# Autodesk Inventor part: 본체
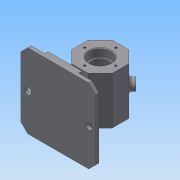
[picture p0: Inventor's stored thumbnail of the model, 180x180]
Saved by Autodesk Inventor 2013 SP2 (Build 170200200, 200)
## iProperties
Created: 2018-06
Part Number: 본체
Material: 일반
Document SubType Name: Modeling
Designer: Administrator
Density: 1 g/cm^3
Author: Administrator
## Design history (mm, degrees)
sketch "스케치1"
  geometry: L1 (-55, -57)-(55, -57); L2 (55, -57)-(55, -62); L3 (55, -62)-(-55, -62); L4 (-55, -62)-(-55, -57); L5 (12.426, 30)-(30, 12.426); L6 (30, 12.426)-(30, -12.426); L7 (30, -12.426)-(12.426, -30); L8 (12.426, -30)-(-12.426, -30); L9 (-12.426, -30)-(-30, -12.426); L10 (-30, -12.426)-(-30, 12.426); L11 (-30, 12.426)-(-12.426, 30); L12 (-12.426, 30)-(12.426, 30); L13 (0, 0)-(-12.426, 30); L14 (0, 0)-(12.426, 30); L15 (-25, -57)-(25, -57); L16 (25, -57)-(25, -52); L17 (25, -52)-(-25, -52); L18 (-25, -52)-(-25, -57); C1 r 30 at (0, 0); 4 further points
  constraints: 36 end point, 4 parallel, 3 midpoint, 2 horizontal, 2 perpendicular, 2 vertical alignment, 1 centre point, 1 coincident, 1 horizontal alignment, 1 point on line, 1 tangent, 17 other
  dimensions: "d14" = 60 diameter of C1; "d16" = 110 distance of L2.end L3.end; "d17" = 5 distance of L3.end L1.start; "d18" = 62 distance from line of point (0, 0) L3; "d20" = 60 distance between parallel lines of L6 L10; "d21" = 30 vertical distance of L13.start L11.end; "d24" = 5 distance of L17.end L15.start; "d25" = 50 distance of L16.end L17.end
extrude "돌출1" new body sketch "스케치1" stored distance "d22" = 70; taper "d23" = 0 deg
extrude "돌출2" join sketch "스케치1" stored distance "d26" = 110; taper "d27" = 0 deg
extrude "돌출3" join sketch "스케치1" stored distance "d28" = 110; taper "d29" = 0 deg
sketch "스케치2"
  geometry: L1 (0, 110)-(50, 110) reference; L2 (20, 74)-(20, 36); L3 (30, 36)-(30, 74); A1 r 5 centre (25, 36) between (20, 36) and (30, 36); A2 r 5 centre (25, 74) between (30, 74) and (20, 74); 2 further points
  constraints: 4 end point, 4 point on circle, 4 tangent, 2 centre point, 1 horizontal alignment, 1 midpoint, 1 parallel, 1 perpendicular, 1 vertical alignment
  dimensions: "d30" = 38 distance of A2.centre A1.centre; "d32" = 5 radius of A2
extrude "돌출4" join sketch "스케치2" stored distance "d33" = 110; taper "d34" = 0 deg
sketch "스케치3"
  geometry: 2 further points
  constraints: 1 vertical alignment
  dimensions: "d35" = 23 distance of point (0, 0) point (0, 23)
hole "구멍1" sketch "스케치3" at (0, 23) diameter "d36" = 3.242; stored, may be unused: countersink angle "d40" = 90 deg, drill point angle "d42" = 118 deg; dims "d37" = 8, "d38" = 4, "d39" = 2, "d41" = 10
sketch "스케치4"
  geometry: 1 further point
hole "구멍2" sketch "스케치4" at (0, 0) diameter "d46" = 28; stored, may be unused: countersink angle "d50" = 90 deg, drill point angle "d52" = 0 deg; dims "d47" = 8, "d48" = 32, "d49" = 12, "d51" = 15
hole "구멍3" diameter "d55" = 50; stored, may be unused: countersink angle "d59" = 90 deg, drill point angle "d61" = 0 deg; dims "d53" = 10, "d54" = 10, "d56" = 8, "d57" = 32, "d58" = 12, "d60" = 40
sketch "스케치5"
  geometry: L1 (0, 0)-(26.163, 26.163); L2 (0, 0)-(37, 0)
  constraints: 4 end point, 1 equal length, 1 horizontal
  dimensions: "d62" = 37 distance of L1.start L1.end; "d63" = 45 deg angle of L2 L1
node "작업 평면1"
sketch "스케치6"
  geometry: C1 r 8 at (0, 0); 1 further point
  constraints: 1 centre point, 1 coincident
  dimensions: "d64" = 16 diameter of C1
extrude "돌출5" join sketch "스케치6" stored distance "d66" = 110; taper "d67" = 0 deg
hole "구멍4" diameter "d70" = 8; stored, may be unused: countersink angle "d74" = 90 deg, drill point angle "d76" = 0 deg; dims "d68" = 10, "d69" = 10, "d71" = 8, "d72" = 32, "d73" = 12, "d75" = 40
sketch "스케치7"
  geometry: L1 (0, 110)-(0, 0) reference; C1 r 5 at (-10, 55); 2 further points
  constraints: 1 centre point, 1 horizontal alignment, 1 midpoint
  dimensions: "d77" = 10 diameter of C1; "d79" = 10 distance from line of L1 C1.centre
extrude "돌출6" cut sketch "스케치7" stored distance "d80" = 110; taper "d81" = 0 deg
sketch "스케치8"
  geometry: L1 (24.853, 0)-(0, 0) reference; L2 (-17.574, 0)-(-17.574, 70) reference; 2 further points
  constraints: 1 other
  dimensions: "d82" = 35 distance from line of L1 point (12.426, 35); "d83" = 30 distance from line of L2 point (12.426, 35)
feature "엠보싱1" sketch "스케치8" dims "d16" = 110, "d17" = 5, "d18" = 62, "d24" = 5, "d25" = 50, "d84" = 0.5, "d85" = 0
chamfer "모따기1" distance "d86" = 10; stored, may be unused: second distance "d87" = 2, angle "d88" = 45 deg
chamfer "모따기2" distance "d89" = 1; stored, may be unused: second distance "d90" = 2, angle "d91" = 45 deg
fillet "모깎기1" dims "d92" = 0.3, "d93" = 3, "d94" = 1, "d95" = 2
node "솔리드1"
pattern_circular "원형 패턴1" dims angle "d44" = 360 deg
mirror "대칭1"
mirror "대칭2"
